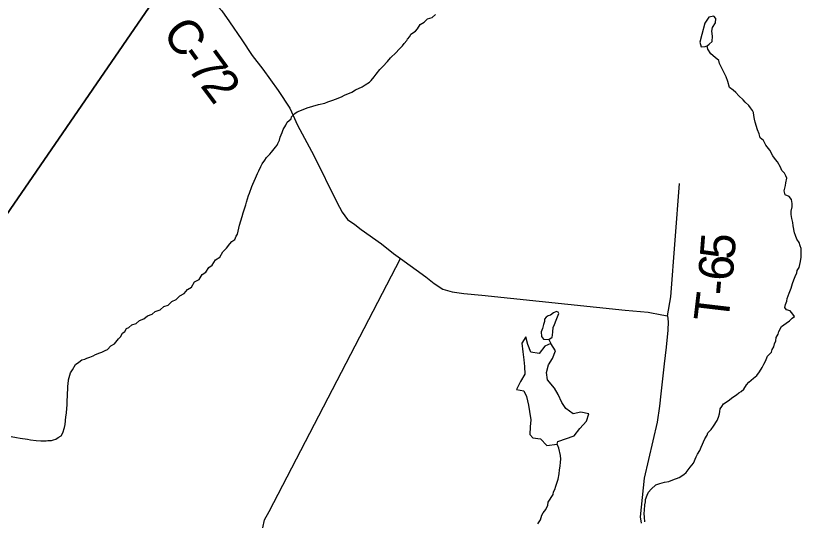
# Model space of a CAD drawing. Extents: x 0 to 39.3, y -3.9 to 22.
# Drawn here: x 4.806 to 6.099, y 14.741 to 15.566 of the extents above; entities that cross this region are included whole.
import ezdxf

# ---------------------------------------------------------------- set-up
doc = ezdxf.new("R2010")
doc.units = 0
for name, color, linetype in [('GM_X_Corporation', 7, 'Continuous'), ('GM_X_County_Road', 7, 'Continuous'), ('GM_X_County_Road_Text', 7, 'Continuous'), ('GM_X_Minor_Lake', 7, 'Continuous'), ('GM_X_Minor_River', 7, 'Continuous'), ('GM_X_Township_Road', 7, 'Continuous'), ('GM_X_Township_Road_Text', 7, 'Continuous')]:
    doc.layers.add(name, color=color, linetype=linetype)

msp = doc.modelspace()

# ---------------------------------------------------------------- linework, layer by layer
at = {"layer": 'GM_X_Corporation'}
for points in [[(6.2667, 17.3782), (6.0256, 17.0319), (5.8398, 16.7652), (5.744, 16.6289), (5.7424, 16.6266), (5.2028, 15.8376), (5.0728, 15.652), (4.2376, 14.4362), (4.2334, 14.4302), (3.9536, 14.0228), (3.9474, 14.0138), (3.8692, 13.9), (7.894, 13.9)], [(1.9, 13.9), (3.8692, 13.9), (3.9474, 14.0138), (3.9536, 14.0228), (4.2334, 14.4302), (4.2376, 14.4362), (5.0728, 15.652)]]:
    msp.add_lwpolyline(points, dxfattribs=at)
at = {"layer": 'GM_X_County_Road'}
for points in [[(5.0743, 15.65), (5.0956, 15.6267), (5.1112, 15.6092), (5.1266, 15.5924), (5.1424, 15.574), (5.155, 15.556), (5.1754, 15.5265), (5.1921, 15.5009), (5.2098, 15.4786), (5.2345, 15.4441), (5.2536, 15.4152), (5.2661, 15.3873), (5.2927, 15.3374), (5.3304, 15.2615), (5.3393, 15.2452), (5.3481, 15.2331), (5.3602, 15.2247), (5.3705, 15.2168), (5.4035, 15.1935), (5.4231, 15.1777), (5.427, 15.1749)], [(5.2096, 14.7287), (5.2123, 14.7421), (5.2197, 14.7556), (5.4348, 15.1693)], [(5.427, 15.1749), (5.4348, 15.1693), (5.4758, 15.1394), (5.4895, 15.1285), (5.5037, 15.1192), (5.519, 15.1146), (5.5383, 15.112), (5.5676, 15.1092), (5.802, 15.0846), (5.8392, 15.0818), (5.8614, 15.0772)], [(5.8614, 15.0772), (5.871, 15.0753), (5.8722, 15.066), (5.8715, 15.052), (5.8685, 15.0241), (5.8654, 14.9971), (5.8601, 14.9483), (5.858, 14.9281), (5.8541, 14.9016), (5.8329, 14.81), (5.8265, 14.7467), (5.8278, 14.7364)]]:
    msp.add_lwpolyline(points, dxfattribs=at)
at = {"layer": 'GM_X_Minor_Lake'}
for points in [[(5.9355, 15.5167), (5.9391, 15.5198), (5.9441, 15.5239), (5.9443, 15.5327), (5.9436, 15.5411), (5.9445, 15.5471), (5.9492, 15.5546), (5.9501, 15.5615), (5.9467, 15.5653), (5.9387, 15.5636), (5.9321, 15.5542), (5.9269, 15.5356), (5.924, 15.5231), (5.9257, 15.5155)], [(5.9257, 15.5155), (5.9322, 15.5158), (5.9355, 15.5167)], [(5.6772, 15.0367), (5.6826, 15.0408), (5.6831, 15.0442), (5.6835, 15.0495), (5.684, 15.0563), (5.686, 15.0612), (5.6888, 15.0684), (5.6932, 15.0794), (5.6921, 15.0813), (5.6894, 15.0825), (5.6848, 15.0803), (5.6798, 15.0769), (5.676, 15.0755), (5.6726, 15.0733), (5.6698, 15.0699)], [(5.6698, 15.0699), (5.6698, 15.0661), (5.6682, 15.0612), (5.6666, 15.0551), (5.6646, 15.0494), (5.6648, 15.0415), (5.6681, 15.0372), (5.6772, 15.0367)], [(5.6908, 14.8659), (5.6918, 14.8699), (5.7186, 14.8793), (5.7275, 14.8913), (5.7383, 14.9033), (5.7424, 14.9154), (5.7291, 14.9179), (5.7165, 14.9155), (5.7045, 14.924), (5.6983, 14.934), (5.6924, 14.9467), (5.6865, 14.9574), (5.675, 14.9709), (5.6733, 14.9828), (5.6765, 14.9956), (5.6828, 15.0058), (5.6879, 15.0182), (5.6802, 15.0302), (5.6702, 15.0258), (5.6613, 15.0141), (5.6477, 15.0159), (5.6426, 15.0289), (5.6394, 15.0411), (5.6327, 15.0306), (5.6344, 15.0165), (5.6364, 15.0036), (5.637, 14.9929), (5.6376, 14.98), (5.6309, 14.9683), (5.6242, 14.9551), (5.6363, 14.953), (5.6407, 14.9434), (5.6435, 14.9293), (5.6456, 14.919), (5.6477, 14.9057), (5.6467, 14.8939), (5.6457, 14.8817)], [(5.6457, 14.8817), (5.6506, 14.8759), (5.6631, 14.8746), (5.6735, 14.8638), (5.6908, 14.8659)]]:
    msp.add_lwpolyline(points, dxfattribs=at)
at = {"layer": 'GM_X_Minor_River'}
for points in [[(5.1817, 15.257), (5.183, 15.2615), (5.1862, 15.2725), (5.1878, 15.2763), (5.1914, 15.2872), (5.1934, 15.291), (5.1974, 15.3008), (5.2009, 15.3084), (5.2029, 15.3126), (5.2061, 15.3197), (5.2084, 15.3239), (5.2127, 15.3303), (5.2155, 15.3344), (5.2209, 15.34), (5.224, 15.343), (5.2283, 15.3483), (5.2303, 15.3513), (5.233, 15.3547), (5.2342, 15.3573), (5.2366, 15.363), (5.2378, 15.3675), (5.241, 15.3751), (5.243, 15.38), (5.2473, 15.3875), (5.2496, 15.3921), (5.2558, 15.3977), (5.2563, 15.4011), (5.2617, 15.4063), (5.2656, 15.4089), (5.2755, 15.4129), (5.282, 15.4155), (5.3004, 15.4209), (5.3107, 15.4234), (5.3157, 15.4252), (5.3241, 15.4281), (5.3284, 15.4299), (5.3383, 15.4336), (5.3433, 15.4365), (5.3548, 15.4413), (5.361, 15.445), (5.3721, 15.4501), (5.3767, 15.4531), (5.3841, 15.4575), (5.3864, 15.4605), (5.3915, 15.4665), (5.3946, 15.4707), (5.4008, 15.4782), (5.4055, 15.483), (5.4136, 15.4916), (5.4183, 15.4973), (5.4276, 15.5062), (5.4318, 15.5107), (5.438, 15.5171), (5.4404, 15.5205), (5.4447, 15.5254), (5.4462, 15.528), (5.4497, 15.5321), (5.4517, 15.5359), (5.459, 15.5411), (5.4625, 15.5449), (5.4669, 15.552), (5.4734, 15.5557), (5.4788, 15.5613), (5.4861, 15.5635), (5.4919, 15.568)], [(6.0822, 15.1457), (6.0826, 15.1499), (6.0862, 15.1548), (6.0882, 15.1643), (6.0891, 15.1715), (6.0894, 15.1856), (6.0876, 15.1898), (6.0861, 15.1955), (6.0824, 15.2009), (6.0802, 15.2067), (6.0784, 15.2113), (6.0763, 15.2227), (6.0757, 15.2281), (6.0739, 15.2349), (6.0729, 15.241), (6.073, 15.2464), (6.0746, 15.254), (6.0747, 15.2593), (6.0733, 15.2658), (6.0696, 15.2708), (6.0632, 15.2736), (6.0614, 15.2797), (6.0626, 15.2842), (6.0635, 15.2888), (6.0643, 15.293), (6.066, 15.3005), (6.0645, 15.3044), (6.0619, 15.309), (6.0578, 15.3132), (6.0556, 15.3186), (6.0508, 15.3271), (6.0475, 15.3309), (6.043, 15.3371), (6.0379, 15.3463), (6.0315, 15.3544), (6.0279, 15.3621), (6.0222, 15.3668), (6.0208, 15.3733), (6.0179, 15.3798), (6.0139, 15.3924), (6.0133, 15.397), (6.0122, 15.4031), (6.0112, 15.4077), (6.0097, 15.4115), (6.0064, 15.4154), (6.0038, 15.4196), (5.9978, 15.4247), (5.9944, 15.4285), (5.9877, 15.4351), (5.9825, 15.4405), (5.978, 15.4444), (5.9723, 15.4487), (5.9695, 15.4586), (5.9666, 15.4663), (5.9559, 15.4878), (5.9549, 15.4928), (5.9489, 15.4978), (5.9417, 15.504), (5.9366, 15.5117), (5.9355, 15.5167)], [(4.7984, 14.8783), (4.8071, 14.8767), (4.8132, 14.8754), (4.825, 14.8737), (4.8299, 14.8728), (4.839, 14.8719), (4.8466, 14.8714), (4.8554, 14.8713), (4.8584, 14.8716), (4.8615, 14.8715), (4.8641, 14.8719), (4.8676, 14.873), (4.8714, 14.874), (4.8753, 14.8766), (4.8799, 14.8792), (4.883, 14.8841), (4.8855, 14.8932), (4.8867, 14.8981), (4.8877, 14.9103), (4.8886, 14.9164), (4.8891, 14.9244), (4.8899, 14.9293), (4.8897, 14.9384), (4.8906, 14.943), (4.8909, 14.9609), (4.8913, 14.9639), (4.8918, 14.9707), (4.8934, 14.9745), (4.8951, 14.9825), (4.8986, 14.987), (4.9033, 14.9961), (4.9091, 14.9998), (4.9137, 15.0035), (4.9187, 15.0045), (4.9218, 15.0064), (4.9271, 15.0078), (4.9321, 15.0104), (4.9363, 15.0122), (4.9432, 15.0148), (4.9463, 15.0159), (4.9521, 15.0188), (4.9555, 15.0207), (4.9613, 15.0263), (4.9671, 15.03), (4.9737, 15.0379), (4.9768, 15.0412), (4.9804, 15.0473), (4.9839, 15.0502), (4.987, 15.0548), (4.9908, 15.0566), (4.9955, 15.0611), (5.0027, 15.0632), (5.0082, 15.0681), (5.0154, 15.0706), (5.0212, 15.0755), (5.0285, 15.078), (5.0339, 15.0829), (5.0416, 15.0854), (5.0478, 15.0906), (5.0551, 15.0932), (5.0609, 15.0988), (5.0682, 15.1021), (5.074, 15.1085), (5.0809, 15.1118), (5.0867, 15.1185), (5.0929, 15.1226), (5.098, 15.1309), (5.1053, 15.1349), (5.1104, 15.1432), (5.1165, 15.1469), (5.1213, 15.1545), (5.127, 15.1586), (5.1321, 15.1672), (5.1391, 15.1717), (5.1442, 15.1803), (5.1504, 15.1859), (5.1558, 15.1935), (5.1589, 15.1968), (5.164, 15.2006), (5.1663, 15.2058), (5.1683, 15.2092), (5.1704, 15.2191), (5.1716, 15.2236), (5.1757, 15.2377), (5.1777, 15.2437), (5.1817, 15.257)], [(5.8339, 14.7385), (5.8332, 14.7462), (5.8326, 14.7523), (5.8331, 14.758), (5.834, 14.7663), (5.8348, 14.7713), (5.8349, 14.7751), (5.8377, 14.7826), (5.8397, 14.7872), (5.8444, 14.7924), (5.8517, 14.7991), (5.8582, 14.8017), (5.8659, 14.8038), (5.8731, 14.8049), (5.8797, 14.8074), (5.89, 14.8114), (5.8977, 14.8162), (5.9016, 14.8196), (5.9082, 14.8282), (5.9133, 14.8346), (5.9176, 14.8448), (5.92, 14.8493), (5.9239, 14.8554), (5.9259, 14.8607), (5.9319, 14.8743), (5.9358, 14.8803), (5.9366, 14.8841), (5.942, 14.8897), (5.9463, 14.8953), (5.9522, 14.9047), (5.9542, 14.9097), (5.9558, 14.9153), (5.9567, 14.9191), (5.9571, 14.9233), (5.9599, 14.9271), (5.9622, 14.9316), (5.9715, 14.9379), (5.9761, 14.9413), (5.9834, 14.9465), (5.9873, 14.9494), (5.9911, 14.9517), (5.9954, 14.9554), (6.0001, 14.9629), (6.0036, 14.967), (6.0117, 14.9734), (6.0167, 14.9782), (6.0214, 14.9839), (6.0257, 14.991), (6.0281, 14.9963), (6.0309, 15.0016), (6.0344, 15.0095), (6.0406, 15.0159), (6.0422, 15.0204), (6.0446, 15.025), (6.0458, 15.0295), (6.0478, 15.0348), (6.0487, 15.0401), (6.0515, 15.0458), (6.0527, 15.0499), (6.057, 15.0579), (6.0651, 15.0638), (6.0705, 15.0675), (6.0744, 15.0716), (6.0786, 15.0742), (6.0756, 15.0781), (6.0712, 15.0835), (6.0655, 15.0855), (6.0629, 15.0893), (6.0637, 15.0943), (6.0657, 15.0996), (6.0662, 15.1041), (6.0698, 15.1124), (6.073, 15.1208), (6.075, 15.1283), (6.0774, 15.1344), (6.0794, 15.1397), (6.0822, 15.1457)], [(5.6772, 15.0367), (5.6802, 15.0302)], [(5.6591, 14.7355), (5.6634, 14.7419), (5.6658, 14.7498), (5.6678, 14.7536), (5.6721, 14.7592), (5.6753, 14.766), (5.6761, 14.771), (5.6839, 14.7834), (5.6848, 14.7879), (5.6868, 14.7917), (5.6884, 14.797), (5.6924, 14.8087), (5.6937, 14.8175), (5.6946, 14.8239), (5.6954, 14.83), (5.6963, 14.8365), (5.6964, 14.841), (5.6961, 14.8471), (5.6933, 14.859), (5.6908, 14.8659)]]:
    msp.add_lwpolyline(points, dxfattribs=at)
at = {"layer": 'GM_X_Township_Road'}
msp.add_lwpolyline([(5.871, 15.0753), (5.8764, 15.1064), (5.8904, 15.292)], dxfattribs=at)

# ---------------------------------------------------------------- texts
at = {"layer": 'GM_X_County_Road_Text'}
for s, rotation, p in [('C', 305.7407, (5.0438, 15.5379)), ('-', 305.8498, (5.0711, 15.4999)), ('7', 306.213, (5.085, 15.4807)), ('2', 306.992, (5.1062, 15.4518))]:
    msp.add_text(s, height=0.0568, rotation=rotation, dxfattribs=at).set_placement(p)
at = {"layer": 'GM_X_Township_Road_Text'}
for s, rotation, p in [('5', 85.4795, (5.98, 15.1664)), ('6', 85.3634, (5.9772, 15.1313)), ('-', 84.888, (5.9751, 15.1076)), ('T', 83.2604, (5.9699, 15.0636))]:
    msp.add_text(s, height=0.0568, rotation=rotation, dxfattribs=at).set_placement(p)

doc.saveas('drawing.dxf')
